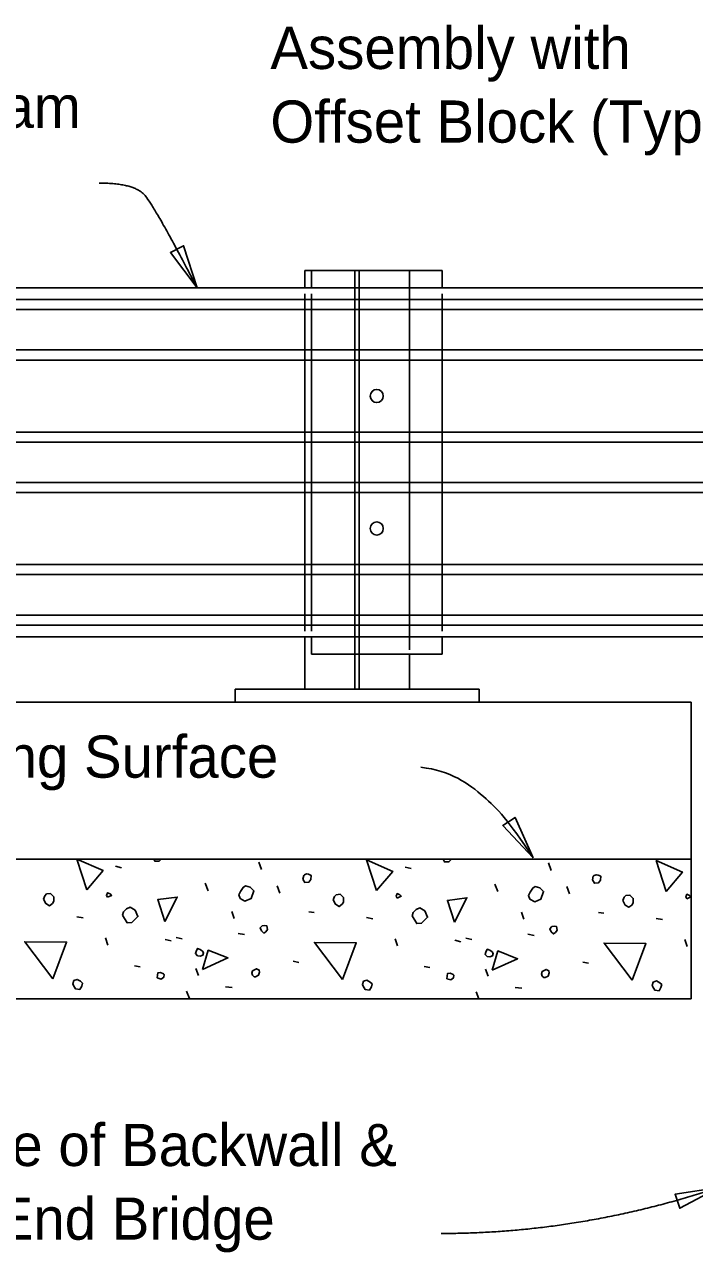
# Model space of a CAD drawing. Extents: x 21587 to 21659.1, y 56113.9 to 56155.9.
# Drawn here: x 21610.3 to 21613.5, y 56132.17 to 56138.04 of the extents above; entities that cross this region are included whole.
import ezdxf

# ---------------------------------------------------------------- set-up
doc = ezdxf.new("R2010")
doc.units = 0
for name, color, linetype in [('AdhocPoint_dp', 7, 'Continuous'), ('Border', 7, 'Continuous'), ('Patterning', 7, 'Continuous'), ('PlotBorder_dp', 7, 'Continuous'), ('SheetBorder_dp', 7, 'Continuous'), ('TextMisc', 7, 'Continuous')]:
    doc.layers.add(name, color=color, linetype=linetype)

msp = doc.modelspace()

# ---------------------------------------------------------------- linework, layer by layer
at = {"layer": 'AdhocPoint_dp'}
for p, q in [((21607.3117, 56134.8009), (21613.4854, 56134.8009)), ((21613.4854, 56134.8008), (21613.4854, 56133.3842)), ((21613.4854, 56134.0509), (21607.3117, 56134.0509)), ((21607.3117, 56133.3843), (21613.4854, 56133.3843))]:
    msp.add_line(p, q, dxfattribs=at)
at = {"layer": 'Border'}
for p, q in [((21611.6393, 56136.8635), (21612.1393, 56136.8635)), ((21611.6393, 56136.8635), (21611.6393, 56136.7802)), ((21619.5663, 56136.7801), (21607.3117, 56136.7801)), ((21607.3117, 56136.7246), (21619.5663, 56136.7246)), ((21607.3117, 56136.6764), (21619.5663, 56136.6764)), ((21607.3117, 56136.4835), (21619.5663, 56136.4835)), ((21607.3117, 56136.4353), (21619.5663, 56136.4353)), ((21607.3117, 56136.0914), (21619.5663, 56136.0914)), ((21607.3117, 56136.0431), (21619.5663, 56136.0431)), ((21607.3117, 56135.8503), (21619.5663, 56135.8503)), ((21607.3117, 56135.8022), (21619.5663, 56135.8022)), ((21607.3117, 56135.4582), (21619.5663, 56135.4582)), ((21607.3117, 56135.41), (21619.5663, 56135.41)), ((21607.3117, 56135.2172), (21619.5663, 56135.2172)), ((21607.3117, 56135.169), (21619.5663, 56135.169)), ((21619.5663, 56135.1134), (21607.3117, 56135.1134)), ((21611.6393, 56135.1135), (21611.6393, 56134.8635)), ((21612.1393, 56135.0302), (21612.1393, 56134.8635)), ((21611.306, 56134.8635), (21612.4726, 56134.8635)), ((21611.306, 56134.801), (21611.306, 56134.8635)), ((21611.8268, 56134.8635), (21612.3268, 56134.8635)), ((21612.4726, 56134.8635), (21612.4726, 56134.801)), ((21611.306, 56134.801), (21612.4726, 56134.801))]:
    msp.add_line(p, q, dxfattribs=at)
for centre in [(21611.983, 56136.2634), (21611.983, 56135.6303)]:
    msp.add_circle(centre, 0.0312, dxfattribs=at)
at = {"layer": 'Patterning'}
for p, q in [((21611.8789, 56134.8635), (21611.8789, 56136.8635)), ((21611.8997, 56134.8635), (21611.8997, 56136.8635)), ((21612.1393, 56136.8635), (21612.1393, 56135.0505)), ((21611.6393, 56136.7516), (21611.6393, 56135.1398))]:
    msp.add_line(p, q, dxfattribs=at)
at = {"layer": 'PlotBorder_dp'}
for points in [[(21611.124, 56136.7801), (21611.0597, 56136.9813), (21610.997, 56136.9489)], [(21612.7308, 56134.0576), (21612.6444, 56134.2503), (21612.5857, 56134.211)], [(21613.6179, 56132.4823), (21613.4091, 56132.4504), (21613.4313, 56132.3834)]]:
    msp.add_lwpolyline(points, close=True, dxfattribs=at)
for points, degree in [([(21610.6563, 56137.2803), (21610.8191, 56137.2803), (21610.9206, 56137.1735), (21611.124, 56136.7801)], 2), ([(21612.194, 56134.4896), (21612.3358, 56134.4753), (21612.5127, 56134.3451), (21612.6101, 56134.2379), (21612.7308, 56134.0575)], 3), ([(21613.6179, 56132.4823), (21612.9542, 56132.2627), (21612.2905, 56132.2627)], 2)]:
    msp.add_open_spline(points, degree=degree, dxfattribs=at)
at = {"layer": 'TextMisc'}
for p, q in [((21611.6705, 56136.8635), (21612.2955, 56136.8635)), ((21611.6705, 56136.8635), (21611.6705, 56136.7802)), ((21612.2955, 56136.8635), (21612.2955, 56136.7802)), ((21611.6705, 56136.7516), (21611.6705, 56135.1398)), ((21612.2955, 56136.7516), (21612.2955, 56135.1398)), ((21611.6705, 56135.0302), (21611.6705, 56135.1135)), ((21612.2955, 56135.0302), (21612.2955, 56135.1135)), ((21611.6705, 56135.0302), (21612.2955, 56135.0302)), ((21610.7346, 56134.0167), (21610.7629, 56134.0096)), ((21611.4329, 56134.0008), (21611.4187, 56134.0362)), ((21612.1193, 56134.0132), (21612.1476, 56134.0061)), ((21612.8175, 56133.9973), (21612.8034, 56134.0326)), ((21611.1765, 56133.9), (21611.1624, 56133.9354)), ((21611.5206, 56133.8883), (21611.5065, 56133.9237)), ((21612.5612, 56133.8965), (21612.5471, 56133.9319)), ((21612.9053, 56133.8848), (21612.8912, 56133.9201)), ((21610.5496, 56133.7752), (21610.5797, 56133.7699)), ((21611.302, 56133.7675), (21611.2897, 56133.801)), ((21611.6585, 56133.7999), (21611.6833, 56133.7964)), ((21611.9343, 56133.7716), (21611.9643, 56133.7663)), ((21612.6867, 56133.7639), (21612.6743, 56133.7975)), ((21613.0432, 56133.7964), (21613.0679, 56133.7928)), ((21613.319, 56133.7681), (21613.349, 56133.7628)), ((21610.6981, 56133.6408), (21610.6857, 56133.6744)), ((21610.9721, 56133.6673), (21611.0004, 56133.6603)), ((21611.0245, 56133.6773), (21611.0528, 56133.6702)), ((21611.3209, 56133.6956), (21611.3509, 56133.6903)), ((21612.0828, 56133.6373), (21612.0704, 56133.6709)), ((21612.3568, 56133.6638), (21612.3851, 56133.6567)), ((21612.4092, 56133.6738), (21612.4375, 56133.6667)), ((21612.7055, 56133.6921), (21612.7356, 56133.6868)), ((21613.4674, 56133.6337), (21613.4551, 56133.6673)), ((21610.8254, 56133.5418), (21610.8519, 56133.5365)), ((21611.5843, 56133.563), (21611.6108, 56133.5577)), ((21612.21, 56133.5383), (21612.2366, 56133.533)), ((21612.9689, 56133.5595), (21612.9955, 56133.5542)), ((21611.1306, 56133.4947), (21611.1182, 56133.5283)), ((21612.5152, 56133.4912), (21612.5029, 56133.5248)), ((21611.0881, 56133.3851), (21611.074, 56133.4205)), ((21611.2608, 56133.4411), (21611.2926, 56133.4375)), ((21612.4717, 56133.3843), (21612.4587, 56133.4169)), ((21612.6454, 56133.4375), (21612.6773, 56133.434))]:
    msp.add_line(p, q, dxfattribs=at)
for points in [[(21610.5973, 56133.9042), (21610.5496, 56134.0509), (21610.6751, 56133.9961), (21610.5973, 56133.9042)], [(21610.9179, 56134.0509), (21610.922, 56134.0415), (21610.9184, 56134.045)], [(21610.922, 56134.0415), (21610.9432, 56134.0415), (21610.9527, 56134.0509)], [(21611.982, 56133.9007), (21611.9343, 56134.0474), (21612.0598, 56133.9926), (21611.982, 56133.9007)], [(21612.3017, 56134.0509), (21612.3013, 56134.0503), (21612.3067, 56134.0379), (21612.3031, 56134.0415)], [(21612.3067, 56134.0379), (21612.3279, 56134.0379), (21612.3385, 56134.0485), (21612.3378, 56134.0509)], [(21613.3667, 56133.8971), (21613.319, 56134.0439), (21613.4445, 56133.9891), (21613.3667, 56133.8971)], [(21611.6302, 56133.9555), (21611.6391, 56133.9396), (21611.6585, 56133.9413), (21611.6673, 56133.9537), (21611.6691, 56133.9731), (21611.6567, 56133.9785), (21611.6479, 56133.9802), (21611.6373, 56133.9767), (21611.6338, 56133.9731), (21611.6302, 56133.9555)], [(21613.0149, 56133.9519), (21613.0237, 56133.936), (21613.0432, 56133.9378), (21613.052, 56133.9502), (21613.0538, 56133.9696), (21613.0414, 56133.9749), (21613.0326, 56133.9767), (21613.022, 56133.9731), (21613.0184, 56133.9696), (21613.0149, 56133.9519)], [(21610.3905, 56133.86), (21610.4011, 56133.8388), (21610.4188, 56133.8282), (21610.4329, 56133.8388), (21610.44, 56133.8494), (21610.44, 56133.8706), (21610.4241, 56133.8865), (21610.4046, 56133.8848), (21610.3958, 56133.8759), (21610.3905, 56133.86)], [(21610.6963, 56133.8689), (21610.7158, 56133.8777), (21610.7087, 56133.8848), (21610.6963, 56133.8901), (21610.691, 56133.8777), (21610.6963, 56133.8689)], [(21611.3303, 56133.8629), (21611.3533, 56133.8505), (21611.3834, 56133.8629), (21611.3957, 56133.9), (21611.3781, 56133.9177), (21611.3551, 56133.923), (21611.3445, 56133.916), (21611.3321, 56133.8965), (21611.3233, 56133.8806), (21611.3303, 56133.8629)], [(21611.7752, 56133.8565), (21611.7858, 56133.8353), (21611.8035, 56133.8247), (21611.8176, 56133.8353), (21611.8247, 56133.8459), (21611.8247, 56133.8671), (21611.8088, 56133.883), (21611.7893, 56133.8812), (21611.7805, 56133.8724), (21611.7752, 56133.8565)], [(21612.081, 56133.8653), (21612.1004, 56133.8742), (21612.0934, 56133.8812), (21612.081, 56133.8865), (21612.0757, 56133.8742), (21612.081, 56133.8653)], [(21612.715, 56133.8594), (21612.738, 56133.847), (21612.768, 56133.8594), (21612.7804, 56133.8965), (21612.7627, 56133.9142), (21612.7398, 56133.9195), (21612.7291, 56133.9124), (21612.7168, 56133.893), (21612.7079, 56133.8771), (21612.715, 56133.8594)], [(21613.4657, 56133.8618), (21613.4851, 56133.8706), (21613.4781, 56133.8777), (21613.4657, 56133.883), (21613.4604, 56133.8706), (21613.4657, 56133.8618)], [(21610.9697, 56133.7533), (21610.9361, 56133.8576), (21611.0298, 56133.87), (21610.9697, 56133.7533)], [(21612.3544, 56133.7498), (21612.3208, 56133.8541), (21612.4145, 56133.8665), (21612.3544, 56133.7498)], [(21613.1599, 56133.8529), (21613.1705, 56133.8317), (21613.1881, 56133.8211), (21613.2023, 56133.8317), (21613.2094, 56133.8423), (21613.2094, 56133.8635), (21613.1934, 56133.8795), (21613.174, 56133.8777), (21613.1652, 56133.8689), (21613.1599, 56133.8529)], [(21610.767, 56133.784), (21610.79, 56133.7469), (21610.813, 56133.7486), (21610.8218, 56133.7575), (21610.8413, 56133.7769), (21610.8289, 56133.807), (21610.8042, 56133.8211), (21610.7865, 56133.814), (21610.7723, 56133.7999), (21610.767, 56133.784)], [(21612.1517, 56133.7805), (21612.1747, 56133.7433), (21612.1977, 56133.7451), (21612.2065, 56133.7539), (21612.226, 56133.7734), (21612.2136, 56133.8034), (21612.1888, 56133.8176), (21612.1712, 56133.8105), (21612.157, 56133.7964), (21612.1517, 56133.7805)], [(21611.4322, 56133.708), (21611.4428, 56133.6974), (21611.4534, 56133.7044), (21611.4605, 56133.7151), (21611.457, 56133.7327), (21611.4481, 56133.7345), (21611.4358, 56133.7327), (21611.4252, 56133.7221), (21611.4322, 56133.708)], [(21612.8169, 56133.7044), (21612.8275, 56133.6938), (21612.8381, 56133.7009), (21612.8452, 56133.7115), (21612.8417, 56133.7292), (21612.8328, 56133.731), (21612.8204, 56133.7292), (21612.8098, 56133.7186), (21612.8169, 56133.7044)], [(21610.4347, 56133.4799), (21610.3003, 56133.6567), (21610.5001, 56133.655), (21610.4347, 56133.4799)], [(21611.8194, 56133.4764), (21611.685, 56133.6532), (21611.8848, 56133.6514), (21611.8194, 56133.4764)], [(21613.2041, 56133.4729), (21613.0697, 56133.6496), (21613.2695, 56133.6479), (21613.2041, 56133.4729)], [(21611.127, 56133.5889), (21611.1394, 56133.5871), (21611.1518, 56133.5925), (21611.1553, 56133.6031), (21611.15, 56133.6119), (21611.1394, 56133.619), (21611.127, 56133.6243), (21611.12, 56133.6101), (21611.1164, 56133.5995), (21611.127, 56133.5889)], [(21611.1494, 56133.5241), (21611.1777, 56133.6161), (21611.2714, 56133.5789), (21611.1494, 56133.5241)], [(21612.5117, 56133.5854), (21612.5241, 56133.5836), (21612.5365, 56133.5889), (21612.54, 56133.5995), (21612.5347, 56133.6084), (21612.5241, 56133.6154), (21612.5117, 56133.6207), (21612.5046, 56133.6066), (21612.5011, 56133.596), (21612.5117, 56133.5854)], [(21612.5341, 56133.5206), (21612.5624, 56133.6125), (21612.656, 56133.5754), (21612.5341, 56133.5206)], [(21610.5337, 56133.4481), (21610.5425, 56133.4322), (21610.5637, 56133.4287), (21610.5726, 56133.4446), (21610.5761, 56133.4587), (21610.5673, 56133.4676), (21610.5514, 56133.4764), (21610.5355, 56133.4711), (21610.5302, 56133.4552), (21610.5337, 56133.4481)], [(21610.9332, 56133.4835), (21610.9527, 56133.4782), (21610.965, 56133.487), (21610.9668, 56133.4994), (21610.9633, 56133.5029), (21610.9491, 56133.51), (21610.9367, 56133.5082), (21610.935, 56133.4959), (21610.9332, 56133.4835)], [(21611.3969, 56133.4888), (21611.4039, 56133.4888), (21611.4181, 56133.4959), (21611.4234, 56133.5118), (21611.4216, 56133.5206), (21611.4075, 56133.5277), (21611.3898, 56133.5171), (21611.3863, 56133.5065), (21611.3898, 56133.4959), (21611.3969, 56133.4888)], [(21611.9184, 56133.4446), (21611.9272, 56133.4287), (21611.9484, 56133.4251), (21611.9573, 56133.4411), (21611.9608, 56133.4552), (21611.952, 56133.464), (21611.936, 56133.4729), (21611.9201, 56133.4676), (21611.9148, 56133.4517), (21611.9184, 56133.4446)], [(21612.3179, 56133.4799), (21612.3373, 56133.4746), (21612.3497, 56133.4835), (21612.3515, 56133.4959), (21612.3479, 56133.4994), (21612.3338, 56133.5065), (21612.3214, 56133.5047), (21612.3197, 56133.4923), (21612.3179, 56133.4799)], [(21612.7816, 56133.4852), (21612.7886, 56133.4852), (21612.8028, 56133.4923), (21612.8081, 56133.5082), (21612.8063, 56133.5171), (21612.7922, 56133.5241), (21612.7745, 56133.5135), (21612.7709, 56133.5029), (21612.7745, 56133.4923), (21612.7816, 56133.4852)], [(21613.303, 56133.4411), (21613.3119, 56133.4251), (21613.3331, 56133.4216), (21613.3419, 56133.4375), (21613.3455, 56133.4517), (21613.3366, 56133.4605), (21613.3207, 56133.4693), (21613.3048, 56133.464), (21613.2995, 56133.4481), (21613.303, 56133.4411)]]:
    msp.add_lwpolyline(points, dxfattribs=at)

# ---------------------------------------------------------------- texts
at = {"layer": 'PlotBorder_dp'}
for s, p in [('Assembly with ', (21611.4746, 56137.8255)), ('Thrie-Beam ', (21609.1604, 56137.5444)), ('Offset Block (Typ.)', (21611.4746, 56137.4735)), ('Front Face of Backwall &', (21609.0827, 56132.5849)), ('Begin or End Bridge', (21609.0827, 56132.2329))]:
    msp.add_text(s, height=0.2016, dxfattribs=at).set_placement(p)
at = {"layer": 'SheetBorder_dp'}
msp.add_text('Final Riding Surface', height=0.2016, dxfattribs=at).set_placement((21609.0852, 56134.44))

doc.saveas('drawing.dxf')
